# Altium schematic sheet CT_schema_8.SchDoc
size 254 x 194 mm
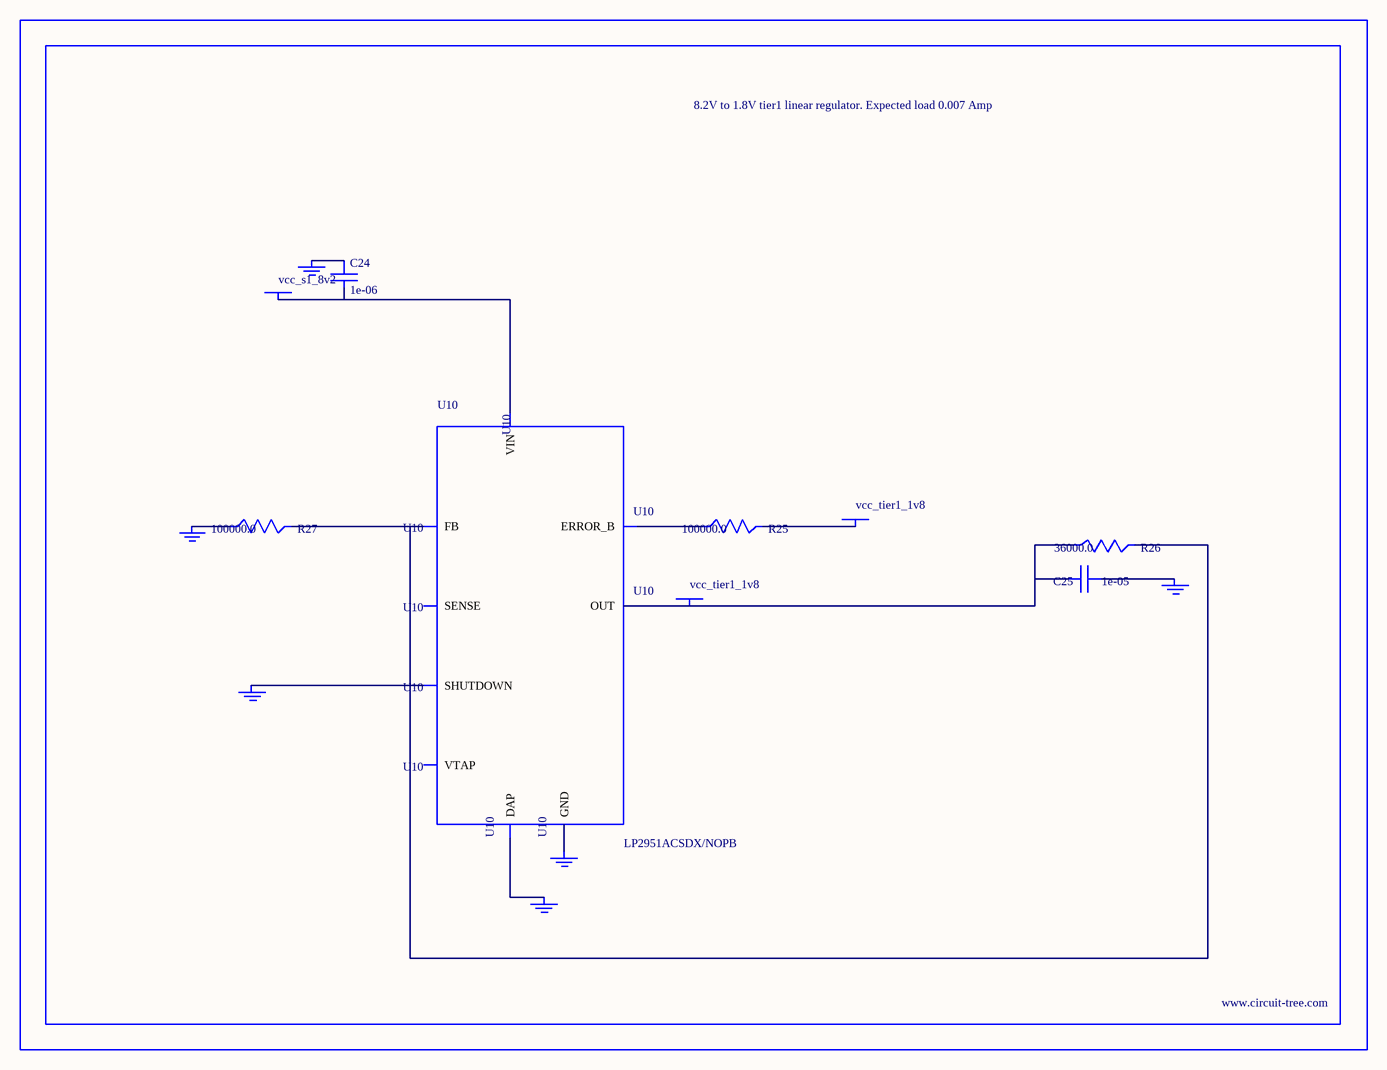
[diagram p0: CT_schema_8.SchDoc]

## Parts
BORDER7  (no value)
C24  1e-06  [C0603]
C25  1e-05  [C0805]
GND_INSTANCE_7_0  (no value)
GND_INSTANCE_7_1  (no value)
GND_INSTANCE_7_2  (no value)
GND_INSTANCE_7_3  (no value)
GND_INSTANCE_7_4  (no value)
GND_INSTANCE_7_5  (no value)
POWER_INSTANCE_7_0  vcc_tier1_1v8
POWER_INSTANCE_7_1  vcc_s1_8v2
POWER_INSTANCE_7_2  vcc_tier1_1v8
R25  100000.0  [R0603]
R26  36000.0  [R0603]
R27  100000.0  [R0603]
U10  LP2951ACSDX/NOPB  [WSON-8]

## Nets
NetC24_1: C24.1 GND_INSTANCE_7_3.0(GND)
NetC24_2: C24.2 POWER_INSTANCE_7_1.0(PWR) U10.8(VIN)
NetC25_1: C25.1 GND_INSTANCE_7_0.0(GND)
NetC25_2: C25.2 POWER_INSTANCE_7_2.0(PWR) R26.1 U10.1(OUT)
NetGND_INSTANCE_7_1_0: GND_INSTANCE_7_1.0(GND) U10.3(SHUTDOWN)
NetGND_INSTANCE_7_2_0: GND_INSTANCE_7_2.0(GND) R27.1
NetGND_INSTANCE_7_4_0: GND_INSTANCE_7_4.0(GND) U10.PAD(DAP)
NetGND_INSTANCE_7_5_0: GND_INSTANCE_7_5.0(GND) U10.4(GND)
NetPOWER_INSTANCE_7_0_0: POWER_INSTANCE_7_0.0(PWR) R25.2
NetR25_1: R25.1 U10.5(ERROR_B)
NetR26_2: R26.2 R27.2 U10.7(FB)

Not connected (* = marked no-connect by the designer): U10 2(SENSE) 6(VTAP)

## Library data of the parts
BORDER7 = BORDER_PAGE7
C24 = C0603C105K3RACTU
C25 = GRM219R60J106ME19D
GND_INSTANCE_7_0-GND_INSTANCE_7_5 = GND
POWER_INSTANCE_7_0-POWER_INSTANCE_7_2 = PWR
R25 R27 = RC0603JR-07100KL
R26 = RC0603JR-0736KL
